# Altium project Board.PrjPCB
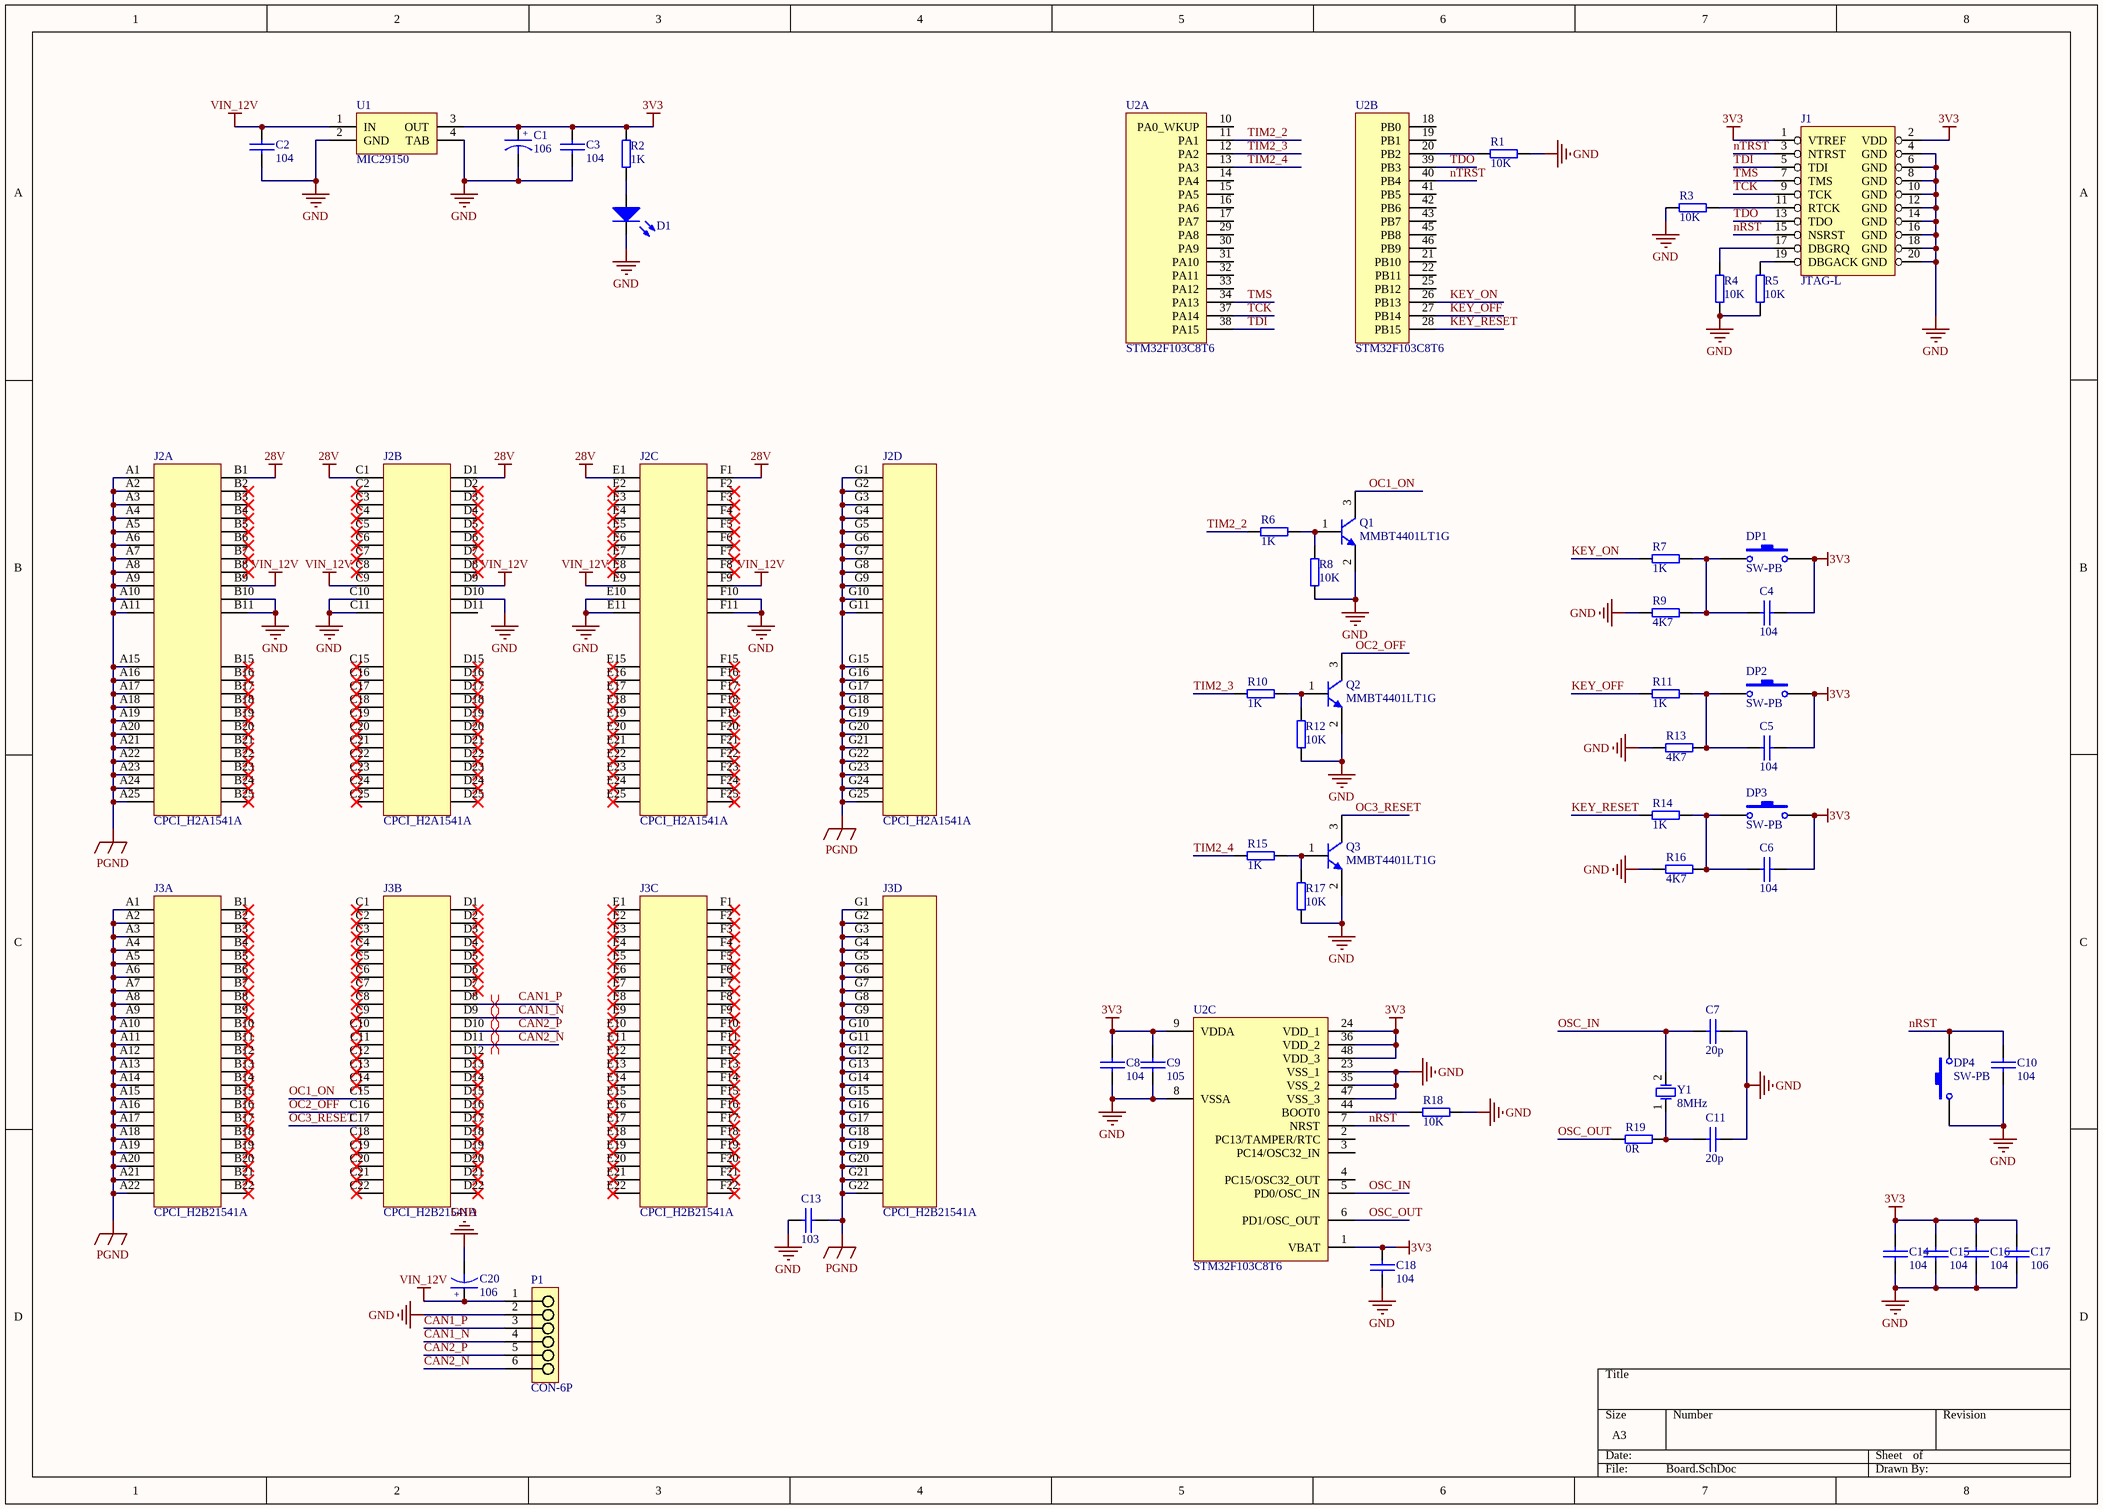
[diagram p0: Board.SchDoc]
1 sheet, 52 parts. Net scope: global (net labels, ports and power ports of the same name join across sheets).
Board file: Board.PcbDoc

## Sheet Board.SchDoc
size A3

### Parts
C1  106  [TC_B_3528]
C2  104  [0805]
C3  104  [0805]
C4  104  [0805]
C5  104  [0805]
C6  104  [0805]
C7  20p  [0805]
C8  104  [0805]
C9  105  [0805]
C10  104  [0805]
C11  20p  [0805]
C13  103  [0805]
C14  104  [0805]
C15  104  [0805]
C16  104  [0805]
C17  106  [0805]
C18  104  [0805]
C20  106  [TC_B_3528]
D1  LED  [0603_LED_S1]  (value not drawn)
DP1  SW-PB  [PB_6X6]
DP2  SW-PB  [PB_6X6]
DP3  SW-PB  [PB_6X6]
DP4  SW-PB  [PB_6X6]
J1  JTAG-L  [JTAG-20P]
J2  CPCI_H2A1541A  [CPCI_H2A1541A]  (parts A,B,C,D of 4)
J3  CPCI_H2B21541A  [CPCI_H2B21541A]  (parts A,B,C,D of 4)
P1  CON-6P  [CON-5.08-6P]
Q1  MMBT4401LT1G  [ONSC-SOT-23-3-318-08_V]
Q2  MMBT4401LT1G  [ONSC-SOT-23-3-318-08_V]
Q3  MMBT4401LT1G  [ONSC-SOT-23-3-318-08_V]
R1  10K  [0805]
R2  1K  [0805]
R3  10K  [0805]
R4  10K  [0805]
R5  10K  [0805]
R6  1K  [0805]
R7  1K  [0805]
R8  10K  [0805]
R9  4K7  [0805]
R10  1K  [0805]
R11  1K  [0805]
R12  10K  [0805]
R13  4K7  [0805]
R14  1K  [0805]
R15  1K  [0805]
R16  4K7  [0805]
R17  10K  [0805]
R18  10K  [0805]
R19  0R  [0805]
U1  MIC29150  [TO263]
U2  STM32F103C8T6  [LQFP48]  (parts A,B,C of 3)
Y1  8MHz  [SMD-3215_2P FC - 135]

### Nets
3V3: C1.1 C3.2 C4.1 C5.1 C6.1 C8.2 C9.2 C14.2 C15.2 C16.2 C17.2 C18.2 DP1.2 DP2.2 DP3.2 J1.1(VTREF) J1.2(VDD) R2.2 U1.3(OUT) U2.1(VBAT) U2.9(VDDA) U2.24(VDD_1) U2.36(VDD_2) U2.48(VDD_3)
28V: J2.B1 J2.C1 J2.D1 J2.E1 J2.F1
GND: C1.2 C2.1 C3.1 C7.1 C8.1 C9.1 C10.1 C11.1 C13.2 C14.1 C15.1 C16.1 C17.1 C18.1 C20.2 D1.K DP4.1 J1.4(GND) J1.6(GND) J1.8(GND) J1.10(GND) J1.12(GND) J1.14(GND) J1.16(GND) J1.18(GND) J1.20(GND) J2.B10 J2.B11 J2.C10 J2.C11 J2.D10 J2.E10 J2.E11 J2.F10 J2.F11 P1.2 Q1.2(E) Q2.2(E) Q3.2(E) R1.2 R3.1 R4.2 R5.2 R8.1 R9.1 R12.1 R13.1 R16.1 R17.1 R18.2 U1.2(GND) U1.4(TAB) U2.8(VSSA) U2.23(VSS_1) U2.35(VSS_2) U2.47(VSS_3)
PGND: C13.1 J2.A1 J2.A2 J2.A3 J2.A4 J2.A5 J2.A6 J2.A7 J2.A8 J2.A9 J2.A10 J2.A11 J2.A15 J2.A16 J2.A17 J2.A18 J2.A19 J2.A20 J2.A21 J2.A22 J2.A23 J2.A24 J2.A25 J2.G1 J2.G2 J2.G3 J2.G4 J2.G5 J2.G6 J2.G7 J2.G8 J2.G9 J2.G10 J2.G11 J2.G15 J2.G16 J2.G17 J2.G18 J2.G19 J2.G20 J2.G21 J2.G22 J2.G23 J2.G24 J2.G25 J3.A1 J3.A2 J3.A3 J3.A4 J3.A5 J3.A6 J3.A7 J3.A8 J3.A9 J3.A10 J3.A11 J3.A12 J3.A13 J3.A14 J3.A15 J3.A16 J3.A17 J3.A18 J3.A19 J3.A20 J3.A21 J3.A22 J3.G1 J3.G2 J3.G3 J3.G4 J3.G5 J3.G6 J3.G7 J3.G8 J3.G9 J3.G10 J3.G11 J3.G12 J3.G13 J3.G14 J3.G15 J3.G16 J3.G17 J3.G18 J3.G19 J3.G20 J3.G21 J3.G22
VIN_12V: C2.2 C20.1 J2.B9 J2.C9 J2.D9 J2.E9 J2.F9 P1.1 U1.1(IN)
CAN1_N: J3.D9 P1.4
CAN1_P: J3.D8 P1.3
CAN2_N: J3.D11 P1.6
CAN2_P: J3.D10 P1.5
KEY_OFF: R11.1 U2.27(PB14)
KEY_ON: R7.1 U2.26(PB13)
KEY_RESET: R14.1 U2.28(PB15)
nRST: C10.2 DP4.2 J1.15(NSRST) U2.7(NRST)
nTRST: J1.3(NTRST) U2.40(PB4)
OC1_ON: J3.C15 Q1.3(C)
OC2_OFF: J3.C16 Q2.3(C)
OC3_RESET: J3.C17 Q3.3(C)
OSC_IN: C7.2 U2.5(PD0/OSC_IN) Y1.2(OSC2)
OSC_OUT: R19.1 U2.6(PD1/OSC_OUT)
TCK: J1.9(TCK) U2.37(PA14)
TDI: J1.5(TDI) U2.38(PA15)
TDO: J1.13(TDO) U2.39(PB3)
TIM2_2: R6.1 U2.11(PA1)
TIM2_3: R10.1 U2.12(PA2)
TIM2_4: R15.1 U2.13(PA3)
TMS: J1.7(TMS) U2.34(PA13)
NetC4_2: C4.2 DP1.1 R7.2 R9.2
NetC5_2: C5.2 DP2.1 R11.2 R13.2
NetC6_2: C6.2 DP3.1 R14.2 R16.2
NetC11_2: C11.2 R19.2 Y1.1(OSC1)
NetD1_A: D1.A R2.1
NetJ1_11: J1.11(RTCK) R3.2
NetJ1_17: J1.17(DBGRQ) R4.1
NetJ1_19: J1.19(DBGACK) R5.1
NetQ1_1: Q1.1(B) R6.2 R8.2
NetQ2_1: Q2.1(B) R10.2 R12.2
NetQ3_1: Q3.1(B) R15.2 R17.2
NetR1_1: R1.1 U2.20(PB2)
NetR18_1: R18.1 U2.44(BOOT0)

Not connected (* = marked no-connect by the designer): J2 B2* B3* B4* B5* B6* B7* B8* B15* B16* B17* B18* B19* B20* B21* B22* B23* B24* B25* C2* C3* C4* C5* C6* C7* C8* C15* C16* C17* C18* C19* C20* C21* C22* C23* C24* C25* D2* D3* D4* D5* D6* D7* D8* D11 D15* D16* D17* D18* D19* D20* D21* D22* D23* D24* D25* E2* E3* E4* E5* E6* E7* E8* E15* E16* E17* E18* E19* E20* E21* E22* E23* E24* E25* F2* F3* F4* F5* F6* F7* F8* F15* F16* F17* F18* F19* F20* F21* F22* F23* F24* F25*; J3 B1* B2* B3* B4* B5* B6* B7* B8* B9* B10* B11* B12* B13* B14* B15* B16* B17* B18* B19* B20* B21* B22* C1* C2* C3* C4* C5* C6* C7* C8* C9* C10* C11* C12* C13* C14* C18* C19* C20* C21* C22* D1* D2* D3* D4* D5* D6* D7* D12* D13* D14* D15* D16* D17* D18* D19* D20* D21* D22* E1* E2* E3* E4* E5* E6* E7* E8* E9* E10* E11* E12* E13* E14* E15* E16* E17* E18* E19* E20* E21* E22* F1* F2* F3* F4* F5* F6* F7* F8* F9* F10* F11* F12* F13* F14* F15* F16* F17* F18* F19* F20* F21* F22*; U2 2(PC13/TAMPER/RTC) 3(PC14/OSC32_IN) 4(PC15/OSC32_OUT) 10(PA0_WKUP) 14(PA4) 15(PA5) 16(PA6) 17(PA7) 18(PB0) 19(PB1) 21(PB10) 22(PB11) 25(PB12) 29(PA8) 30(PA9) 31(PA10) 32(PA11) 33(PA12) 41(PB5) 42(PB6) 43(PB7) 45(PB8) 46(PB9)

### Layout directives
differential pair: CAN1_N, CAN1_P, CAN2_N, CAN2_P

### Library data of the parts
C1 C20 = CAP POL1: Capacitor
C2-C11 C13-C18 = CAP
DP1-DP4 = SW-PB: Key
J1 = JTAG-L: Connector
Q1-Q3 = MMBT4401LT1G: Switching Transistor, NPN Silicon, 3-Pin SOT-23, Pb-Free, Tape and Reel; Manufacturer: On Semiconductor; fT Min (MHz): 250; IC Continuous (A): 0.6
R1-R19 = RES1
U2 = STM32F103C6T6: ST ARM-based 32-bit MCU with 32 KB Flash, USB, CAN, 7 timers, 2 ADCs, 9 com. interfaces
Y1 = XTAL-3215_2P 32.768: 贴片晶振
